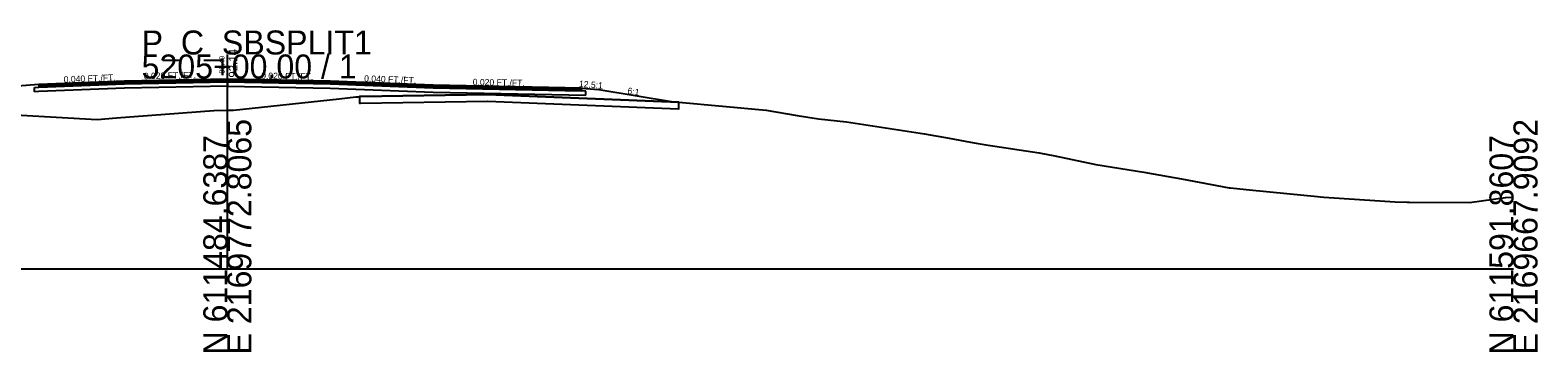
# Model space of a CAD drawing. Extents: x -26 to 1303, y -3010 to 12023.
# Drawn here: x 1127 to 1302.8, y 4490.3 to 4527.8 of the extents above; entities that cross this region are included whole.
import ezdxf

# ---------------------------------------------------------------- set-up
doc = ezdxf.new("R2010")
doc.units = 0
for name, color, linetype in [('RD_GPK_XS_Cell', 7, 'Continuous'), ('RD_XS_Base', 7, 'Continuous'), ('RD_XS_ExGround', 7, 'Continuous'), ('RD_XS_ExPaveRet', 7, 'Continuous'), ('RD_XS_Greenside', 7, 'Continuous'), ('RD_XS_Pave', 7, 'Continuous'), ('RD_XS_PaveOvlay_CP', 7, 'Continuous'), ('RD_XS_TieSlope', 7, 'Continuous'), ('RD_XS_TX_Elev_EX', 7, 'Continuous'), ('RD_XS_TX_Elev_PR', 7, 'Continuous'), ('RD_XS_TX_ShdSlope', 7, 'Continuous'), ('RD_XS_TX_Slope', 7, 'Continuous')]:
    doc.layers.add(name, color=color, linetype=linetype)

msp = doc.modelspace()

# ---------------------------------------------------------------- linework, layer by layer
at = {"layer": 'RD_GPK_XS_Cell'}
for p, q in [((1150, 4500), (1150, 4525)), ((1000, 4500), (1150, 4500)), ((1150, 4500), (1300, 4500))]:
    msp.add_line(p, q, dxfattribs=at)
at = {"layer": 'RD_XS_Base'}
for p, q in [((1127.5, 4521.16), (1128, 4521.18)), ((1127.5, 4520.66), (1127.5, 4521.16)), ((1127.5, 4521.16), (1127.5, 4521.16)), ((1128, 4521.18), (1138, 4521.58)), ((1128, 4521.18), (1128, 4521.18)), ((1138, 4521.08), (1128, 4520.68)), ((1136, 4521.5), (1136, 4521.5)), ((1136, 4521), (1136, 4521)), ((1138, 4521.58), (1150, 4521.82)), ((1150, 4521.32), (1138, 4521.08)), ((1150, 4521.82), (1150, 4521.98)), ((1150, 4521.98), (1150, 4521.32)), ((1150, 4521.82), (1150, 4521.82)), ((1162, 4521.58), (1150, 4521.82)), ((1150, 4521.82), (1150, 4521.82)), ((1150, 4521.82), (1150, 4521.32)), ((1150, 4521.32), (1150, 4521.32)), ((1150, 4521.32), (1162, 4521.08)), ((1150, 4521.32), (1150, 4521.32)), ((1174, 4521.1), (1162, 4521.58)), ((1162, 4521.58), (1162, 4521.58)), ((1162, 4521.08), (1162, 4521.08)), ((1162, 4521.08), (1174, 4520.6)), ((1191.32, 4520.75), (1174, 4521.1)), ((1174, 4521.1), (1174, 4521.1)), ((1191.82, 4520.74), (1191.32, 4520.75)), ((1191.32, 4520.75), (1191.32, 4520.75)), ((1128, 4520.68), (1127.5, 4520.66)), ((1127.5, 4520.66), (1127.5, 4520.66)), ((1127.5, 4520.66), (1127.5, 4520.66)), ((1128, 4520.68), (1128, 4520.68)), ((1174, 4520.6), (1174, 4520.6)), ((1174, 4520.6), (1191.82, 4520.24)), ((1191.82, 4520.24), (1191.82, 4520.74)), ((1191.82, 4520.74), (1191.82, 4520.74)), ((1191.82, 4520.24), (1191.82, 4520.24)), ((1191.82, 4520.24), (1191.82, 4520.24))]:
    msp.add_line(p, q, dxfattribs=at)
at = {"layer": 'RD_XS_ExGround'}
msp.add_lwpolyline([(1115.93, 4518.5), (1127.3, 4517.85), (1134.82, 4517.43), (1137.09, 4517.61), (1148.44, 4518.48), (1149.92, 4518.51), (1150.73, 4518.52), (1163.04, 4519.83), (1165, 4520.05), (1165.26, 4520.07), (1165.42, 4520.09), (1165.52, 4520.09), (1180.35, 4520.32), (1202.63, 4519.43), (1202.65, 4519.43), (1202.67, 4519.43), (1212.86, 4518.51), (1216.46, 4517.88), (1218.93, 4517.51), (1222.2, 4517.14), (1231.32, 4515.76), (1234.18, 4515.25), (1236.68, 4514.79), (1237.34, 4514.66), (1238.75, 4514.42), (1244.67, 4513.51), (1246.5, 4513.17), (1251.29, 4512.18), (1256.9, 4511.27), (1259.74, 4510.77), (1261.29, 4510.5), (1266.84, 4509.45), (1266.98, 4509.43), (1268.81, 4509.24), (1273.95, 4508.73), (1276.77, 4508.46), (1277.87, 4508.34), (1286.19, 4507.82), (1287.58, 4507.76), (1287.86, 4507.76), (1294.87, 4507.72), (1299.07, 4508.3), (1300, 4508.34)], dxfattribs=at)
at = {"layer": 'RD_XS_ExPaveRet'}
for points in [[(1202.63, 4519.43), (1180.35, 4520.32), (1180.35, 4520.32), (1180.35, 4520.32), (1165.52, 4520.09), (1165.52, 4520.09), (1165.42, 4520.09), (1165.42, 4519.34), (1165.42, 4519.34), (1165.52, 4519.34), (1165.52, 4519.34), (1180.35, 4519.57), (1180.35, 4519.57), (1180.35, 4519.57), (1202.63, 4518.68), (1202.63, 4518.68), (1202.65, 4518.68), (1202.65, 4519.43), (1202.65, 4519.43), (1202.63, 4519.43), (1202.63, 4519.43)], [(1202.63, 4519.43), (1180.35, 4520.32), (1165.52, 4520.09), (1165.42, 4520.09), (1165.42, 4519.34), (1165.52, 4519.34), (1180.35, 4519.57), (1202.63, 4518.68), (1202.65, 4518.68), (1202.65, 4519.43), (1202.63, 4519.43)]]:
    msp.add_lwpolyline(points, dxfattribs=at)
at = {"layer": 'RD_XS_Greenside'}
msp.add_line((1193.32, 4520.91), (1202.05, 4519.46), dxfattribs=at)
at = {"layer": 'RD_XS_Pave'}
for p, q in [((1138, 4521.9), (1128, 4521.5)), ((1138, 4521.74), (1128, 4521.34)), ((1128, 4521.34), (1138, 4521.74)), ((1128, 4521.18), (1138, 4521.58)), ((1128, 4521.5), (1128, 4521.5)), ((1128, 4521.5), (1128, 4521.34)), ((1128, 4521.34), (1128, 4521.34)), ((1128, 4521.34), (1128, 4521.18)), ((1128, 4521.34), (1128, 4521.34)), ((1128, 4521.34), (1128, 4521.34)), ((1128, 4521.18), (1128, 4521.18)), ((1128, 4521.18), (1128, 4521.18)), ((1136, 4521.82), (1136, 4521.82)), ((1136, 4521.66), (1136, 4521.66)), ((1136, 4521.66), (1136, 4521.66)), ((1136, 4521.5), (1136, 4521.5)), ((1150, 4522.14), (1138, 4521.9)), ((1150, 4521.98), (1138, 4521.74)), ((1138, 4521.74), (1150, 4521.98)), ((1138, 4521.58), (1150, 4521.82)), ((1162, 4521.9), (1150, 4522.14)), ((1150, 4521.82), (1150, 4521.98)), ((1150, 4521.98), (1162, 4521.74)), ((1162, 4521.74), (1150, 4521.98)), ((1150, 4521.98), (1150, 4521.98)), ((1150, 4521.98), (1150, 4521.82)), ((1150, 4521.82), (1150, 4521.82)), ((1150, 4521.82), (1150, 4521.82)), ((1150, 4521.82), (1150, 4521.82)), ((1150, 4521.82), (1162, 4521.58)), ((1174, 4521.42), (1162, 4521.9)), ((1162, 4521.9), (1162, 4521.9)), ((1162, 4521.74), (1162, 4521.74)), ((1162, 4521.74), (1174, 4521.26)), ((1174, 4521.26), (1162, 4521.74)), ((1162, 4521.74), (1162, 4521.74)), ((1162, 4521.58), (1162, 4521.58)), ((1162, 4521.58), (1174, 4521.1)), ((1191.32, 4521.07), (1174, 4521.42)), ((1174, 4521.42), (1174, 4521.42)), ((1174, 4521.26), (1174, 4521.26)), ((1174, 4521.26), (1191.32, 4520.91)), ((1191.32, 4520.91), (1174, 4521.26)), ((1174, 4521.26), (1174, 4521.26)), ((1174, 4521.1), (1174, 4521.1)), ((1174, 4521.1), (1191.32, 4520.75)), ((1191.32, 4520.91), (1191.32, 4521.07)), ((1191.32, 4521.07), (1191.32, 4521.07)), ((1191.32, 4520.91), (1191.32, 4520.91)), ((1191.32, 4520.91), (1191.32, 4520.91)), ((1191.32, 4520.75), (1191.32, 4520.91)), ((1191.32, 4520.91), (1191.32, 4520.91)), ((1191.32, 4520.75), (1191.32, 4520.75)), ((1191.32, 4520.75), (1191.32, 4520.75))]:
    msp.add_line(p, q, dxfattribs=at)
at = {"layer": 'RD_XS_PaveOvlay_CP'}
for p, q in [((1138, 4521.9), (1128, 4521.5)), ((1128, 4521.5), (1128, 4521.5)), ((1136, 4521.82), (1136, 4521.82)), ((1150, 4522.14), (1138, 4521.9)), ((1162, 4521.9), (1150, 4522.14)), ((1174, 4521.42), (1162, 4521.9)), ((1162, 4521.9), (1162, 4521.9)), ((1191.32, 4521.07), (1174, 4521.42)), ((1174, 4521.42), (1174, 4521.42)), ((1191.32, 4521.07), (1191.32, 4521.07))]:
    msp.add_line(p, q, dxfattribs=at)
at = {"layer": 'RD_XS_TieSlope'}
for p, q in [((1128, 4521.5), (1122, 4521.02)), ((1191.32, 4521.07), (1193.32, 4520.91))]:
    msp.add_line(p, q, dxfattribs=at)

# ---------------------------------------------------------------- texts
at = {"layer": 'RD_GPK_XS_Cell'}
for s, p in [('P_C_SBSPLIT1', (1140, 4525)), ('5205+00.00 / 1', (1140, 4522.2))]:
    msp.add_text(s, height=2.8, dxfattribs=at).set_placement(p)
for s, p in [('E 2169772.8065', (1152.8, 4490)), ('E 2169667.9092', (1302.8, 4490)), ('N 611484.6387', (1150, 4490)), ('N 611591.8607', (1300, 4490))]:
    msp.add_text(s, height=2.8, rotation=90, dxfattribs=at).set_placement(p)
at = {"layer": 'RD_XS_TX_Elev_EX'}
msp.add_text('88.49', height=0.6, rotation=90, dxfattribs=at).set_placement((1149.67, 4522.77))
at = {"layer": 'RD_XS_TX_Elev_PR'}
msp.add_text('92.14', height=1, rotation=90, dxfattribs=at).set_placement((1151.16, 4522.3))
at = {"layer": 'RD_XS_TX_ShdSlope'}
msp.add_text('12.5:1', height=0.75, rotation=355.4261, dxfattribs=at).set_placement((1190.99, 4521.22))
at = {"layer": 'RD_XS_TX_Slope'}
for s, rotation, p in [('0.040 FT./FT.', 2.2906, (1130.93, 4521.71)), ('0.020 FT./FT.', 1.1458, (1140.27, 4522.11)), ('0.020 FT./FT.', 358.8542, (1153.94, 4522.16)), ('0.040 FT./FT.', 357.7094, (1165.94, 4521.84)), ('0.020 FT./FT.', 358.8542, (1178.61, 4521.42)), ('6:1', 350.5377, (1196.62, 4520.42))]:
    msp.add_text(s, height=0.75, rotation=rotation, dxfattribs=at).set_placement(p)

doc.saveas('drawing.dxf')
